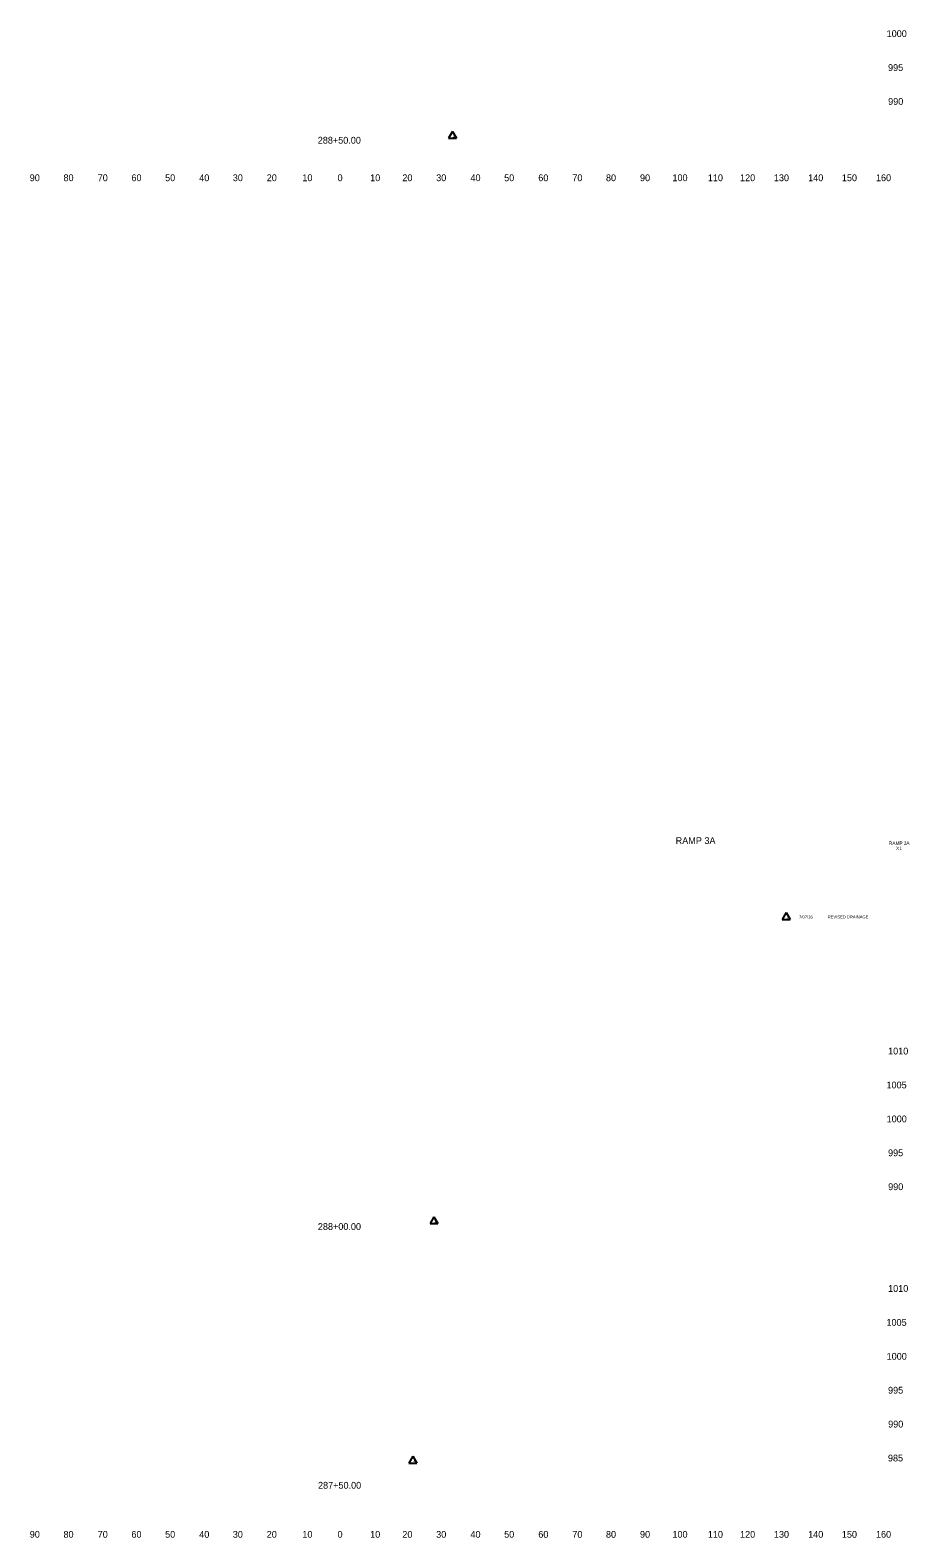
# Model space of a CAD drawing. Extents: x 4286 to 5843, y 4997 to 8804.
# Drawn here: x 5068.6 to 5327.8, y 4997.5 to 5442 of the extents above; entities that cross this region are included whole.
import ezdxf

# ---------------------------------------------------------------- set-up
doc = ezdxf.new("R2010")
doc.units = 0
for name, color, linetype in [('RD_SHT_ID', 7, 'Continuous'), ('RD_SHT_TX', 7, 'Continuous'), ('RD_XS_TX_Offset', 7, 'Continuous'), ('RD_XS_TX_Station', 7, 'Continuous')]:
    doc.layers.add(name, color=color, linetype=linetype)

msp = doc.modelspace()

# ---------------------------------------------------------------- linework, layer by layer
at = {"layer": 'RD_SHT_TX'}
for p, q in [((5193.19, 5412.18), (5192.06, 5410.15)), ((5193.19, 5412.18), (5194.33, 5410.15)), ((5192.06, 5410.15), (5194.33, 5410.15)), ((5291.62, 5181.85), (5290.48, 5179.82)), ((5290.48, 5179.82), (5292.75, 5179.82)), ((5291.62, 5181.85), (5292.75, 5179.82)), ((5187.73, 5092.15), (5186.6, 5090.12)), ((5187.73, 5092.15), (5188.87, 5090.12)), ((5186.6, 5090.12), (5188.87, 5090.12)), ((5181.49, 5021.54), (5180.35, 5019.51)), ((5180.35, 5019.51), (5182.63, 5019.51)), ((5181.49, 5021.54), (5182.63, 5019.51))]:
    msp.add_line(p, q, dxfattribs=at)

# ---------------------------------------------------------------- texts
at = {"layer": 'RD_SHT_ID'}
for s, height, p in [('RAMP 3A', 2, (5259.02, 5202.06)), ('RAMP 3A', 1, (5321.93, 5201.8)), ('X1', 1, (5324.02, 5200.3))]:
    msp.add_text(s, height=height, dxfattribs=at).set_placement(p)
at = {"layer": 'RD_SHT_TX'}
for s, p in [('1', (5193.19, 5410.47)), ('1', (5291.62, 5180.15)), ('7/07/16', (5295.4, 5180.11)), ('REVISED DRAINAGE', (5303.85, 5180.11)), ('1', (5187.73, 5090.45)), ('1', (5181.49, 5019.84))]:
    msp.add_text(s, height=0.88, dxfattribs=at).set_placement(p)
at = {"layer": 'RD_XS_TX_Offset'}
for s, p in [('1000', (5321.24, 5440)), ('995', (5321.66, 5430)), ('990', (5321.69, 5420)), ('90', (5068.5, 5397.5)), ('80', (5078.46, 5397.5)), ('70', (5088.54, 5397.5)), ('60', (5098.5, 5397.5)), ('50', (5108.43, 5397.5)), ('40', (5118.5, 5397.5)), ('30', (5128.39, 5397.5)), ('20', (5138.4, 5397.5)), ('10', (5148.91, 5397.5)), ('0', (5159.3, 5397.5)), ('0', (5159.3, 5397.5)), ('10', (5168.91, 5397.5)), ('20', (5178.4, 5397.5)), ('30', (5188.39, 5397.5)), ('40', (5198.5, 5397.5)), ('50', (5208.43, 5397.5)), ('60', (5218.5, 5397.5)), ('70', (5228.54, 5397.5)), ('80', (5238.46, 5397.5)), ('90', (5248.5, 5397.5)), ('100', (5258.07, 5397.5)), ('110', (5268.51, 5397.5)), ('120', (5278.01, 5397.5)), ('130', (5287.99, 5397.5)), ('140', (5298.1, 5397.5)), ('150', (5308.04, 5397.5)), ('160', (5318.1, 5397.5)), ('1010', (5321.68, 5140)), ('1005', (5321.2, 5130)), ('1000', (5321.24, 5120)), ('995', (5321.66, 5110)), ('990', (5321.69, 5100)), ('1010', (5321.68, 5070)), ('1005', (5321.2, 5060)), ('1000', (5321.24, 5050)), ('995', (5321.66, 5040)), ('990', (5321.69, 5030)), ('985', (5321.63, 5020)), ('90', (5068.5, 4997.5)), ('80', (5078.46, 4997.5)), ('70', (5088.54, 4997.5)), ('60', (5098.5, 4997.5)), ('50', (5108.43, 4997.5)), ('40', (5118.5, 4997.5)), ('30', (5128.39, 4997.5)), ('20', (5138.4, 4997.5)), ('10', (5148.91, 4997.5)), ('0', (5159.3, 4997.5)), ('0', (5159.3, 4997.5)), ('10', (5168.91, 4997.5)), ('20', (5178.4, 4997.5)), ('30', (5188.39, 4997.5)), ('40', (5198.5, 4997.5)), ('50', (5208.43, 4997.5)), ('60', (5218.5, 4997.5)), ('70', (5228.54, 4997.5)), ('80', (5238.46, 4997.5)), ('90', (5248.5, 4997.5)), ('100', (5258.07, 4997.5)), ('110', (5268.51, 4997.5)), ('120', (5278.01, 4997.5)), ('130', (5287.99, 4997.5)), ('140', (5298.1, 4997.5)), ('150', (5308.04, 4997.5)), ('160', (5318.1, 4997.5))]:
    msp.add_text(s, height=2, dxfattribs=at).set_placement(p)
at = {"layer": 'RD_XS_TX_Station'}
for s, p in [('288+50.00', (5153.46, 5408.57)), ('288+00.00', (5153.49, 5088.26)), ('287+50.00', (5153.54, 5011.97))]:
    msp.add_text(s, height=2, dxfattribs=at).set_placement(p)

doc.saveas('drawing.dxf')
